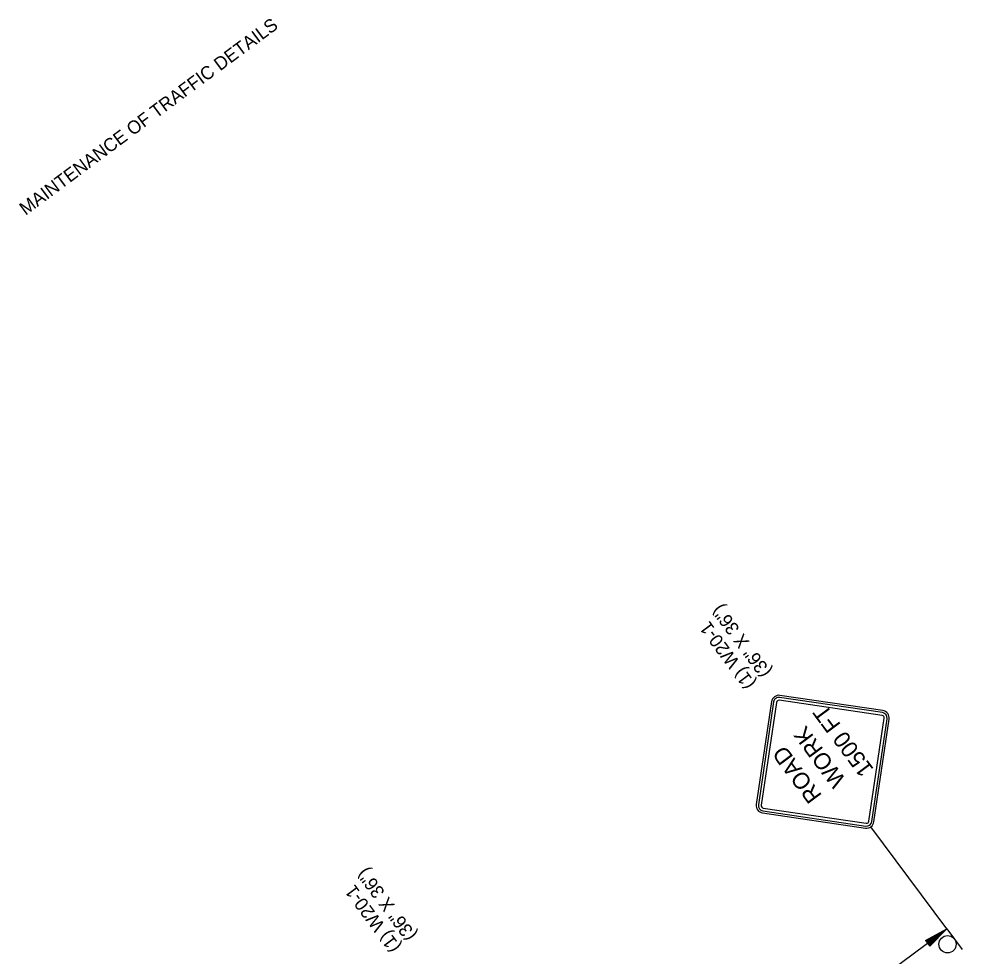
# Model space of a CAD drawing. Extents: x 998982 to 1000626, y 1875366 to 1876934.
# Drawn here: x 999939.8 to 1000368.5, y 1876507.9 to 1876933.9 of the extents above; entities that cross this region are included whole.
import ezdxf

# ---------------------------------------------------------------- set-up
doc = ezdxf.new("R2010")
doc.units = 0
for name, color, linetype in [('P_TC_Signs_Temporary', 7, 'Continuous'), ('R_Border', 7, 'Continuous'), ('R_Border Prem', 7, 'Continuous'), ('R_Draft', 7, 'Continuous'), ('STAMP', 7, 'Continuous')]:
    doc.layers.add(name, color=color, linetype=linetype)

msp = doc.modelspace()

# ---------------------------------------------------------------- linework, layer by layer
at = {"layer": 'P_TC_Signs_Temporary'}
for p, q in [((1000332.1, 1876617.24), (1000285.35, 1876624.15)), ((1000332.29, 1876618.54), (1000285.54, 1876625.45)), ((1000332.42, 1876619.47), (1000285.68, 1876626.37)), ((1000281.85, 1876623.53), (1000274.94, 1876576.78)), ((1000282.78, 1876623.39), (1000275.87, 1876576.65)), ((1000284.08, 1876623.2), (1000277.17, 1876576.46)), ((1000326.14, 1876569.22), (1000333.04, 1876615.96)), ((1000327.44, 1876569.03), (1000334.34, 1876615.77)), ((1000328.36, 1876568.89), (1000335.27, 1876615.63)), ((1000277.79, 1876572.95), (1000324.53, 1876566.05)), ((1000277.93, 1876573.88), (1000324.67, 1876566.97)), ((1000278.12, 1876575.18), (1000324.86, 1876568.27))]:
    msp.add_line(p, q, dxfattribs=at)
for centre, radius, start, end in [((1000285.19, 1876623.03), 3.38, 81.5953, 171.5953), ((1000285.19, 1876623.03), 2.44, 81.5953, 171.5953), ((1000285.19, 1876623.03), 1.12, 81.5953, 171.5953), ((1000331.93, 1876616.13), 1.13, 351.5953, 81.5953), ((1000331.93, 1876616.13), 2.44, 351.5953, 81.5953), ((1000331.93, 1876616.13), 3.38, 351.5953, 81.5953), ((1000278.28, 1876576.29), 3.38, 171.5953, 261.5953), ((1000278.28, 1876576.29), 2.44, 171.5953, 261.5953), ((1000278.28, 1876576.29), 1.13, 171.5953, 261.5953), ((1000325.02, 1876569.39), 3.38, 261.5953, 351.5953), ((1000325.02, 1876569.39), 2.44, 261.5953, 351.5953), ((1000325.02, 1876569.39), 1.12, 261.5953, 351.5953)]:
    msp.add_arc(centre, radius, start, end, dxfattribs=at)
at = {"layer": 'R_Draft'}
for p, q in [((1000361.46, 1876520.31), (1000327.04, 1876566.68)), ((1000200.89, 1876401.08), (1000361.46, 1876520.31)), ((1000351.84, 1876514.98), (1000361.46, 1876520.31)), ((1000352, 1876514.77), (1000360.02, 1876519.2)), ((1000352.18, 1876514.55), (1000358.54, 1876518.07)), ((1000352.34, 1876514.33), (1000357.1, 1876516.96)), ((1000353.32, 1876513.04), (1000357.1, 1876516.96)), ((1000353.49, 1876512.83), (1000358.54, 1876518.07)), ((1000353.66, 1876512.61), (1000360.02, 1876519.2)), ((1000353.83, 1876512.39), (1000361.46, 1876520.31)), ((1000351.84, 1876514.98), (1000353.83, 1876512.39)), ((1000352.51, 1876514.11), (1000355.64, 1876515.84)), ((1000352.67, 1876513.89), (1000354.2, 1876514.73)), ((1000352.99, 1876513.48), (1000354.2, 1876514.73)), ((1000353.16, 1876513.26), (1000355.64, 1876515.84))]:
    msp.add_line(p, q, dxfattribs=at)
at = {"layer": 'STAMP'}
msp.add_line((1000361.46, 1876520.31), (1000368.46, 1876510.87), dxfattribs=at)
msp.add_circle((1000361.82, 1876513.26), 3.92, dxfattribs=at)

# ---------------------------------------------------------------- texts
at = {"layer": 'P_TC_Signs_Temporary'}
for s, p in [('1500 FT', (1000328.55, 1876592.87)), ('WORK', (1000315.96, 1876587.99)), (' ROAD ', (1000306.67, 1876578.66))]:
    msp.add_text(s, height=7.5, rotation=126.5953, dxfattribs=at).set_placement(p)
at = {"layer": 'R_Border'}
msp.add_text('MAINTENANCE OF TRAFFIC DETAILS', height=6, rotation=36.5953, dxfattribs=at).set_placement((999942.87, 1876844.35))
at = {"layer": 'R_Border Prem'}
for s, p in [('(36" X 36")', (1000282.06, 1876637.24)), ('(1) W20-1', (1000274.83, 1876631.87)), ('(36" X 36")', (1000120.84, 1876517.53)), ('(1) W20-1', (1000113.62, 1876512.16))]:
    msp.add_text(s, height=6, rotation=126.5953, dxfattribs=at).set_placement(p)

doc.saveas('drawing.dxf')
